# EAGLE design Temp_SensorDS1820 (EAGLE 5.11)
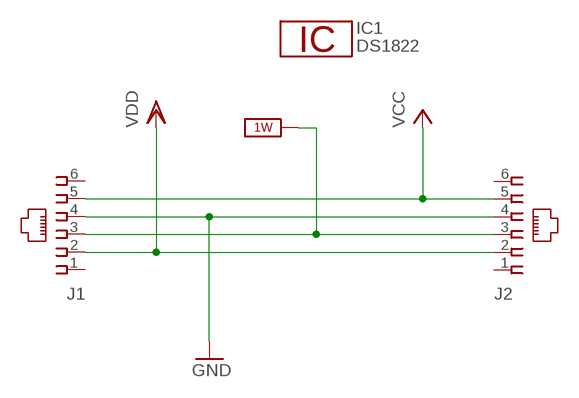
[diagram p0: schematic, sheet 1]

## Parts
IC1  DS1822  [TO92-]
J1  520243-3  [520243-3]
J2  520243-3  [520243-3]

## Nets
1W: J1.3 J2.3 ; supply symbol labelled 1W_SUP
GND: J1.4 J2.4
VCC [12V]: J1.5 J2.5
VDD: J1.2 J2.2
Unconnected: J1.1 J1.6 J2.1 J2.6

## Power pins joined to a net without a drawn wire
1W: IC1.2
GND: IC1.1
VDD: IC1.3

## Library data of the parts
IC1 = 1wire:DS1822: Econo Digital Thermometer This chip provides a onewire thermosensor with approx. 2°C accuracy. A programmable over/undertemperure alarm is available. Notes: Vdd must be applied for accurate measurements at low temperatures, as the parasite power circuit otherwise heats the sensor. If parasite power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
J1 J2 = con-amp:520243-3: AMP connector; OC_FARNELL: unknown; OC_NEWARK: unknown

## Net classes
0 default: width 0.381 mm, drill 0.762 mm
1 12V: width 0.381 mm, drill 0.762 mm

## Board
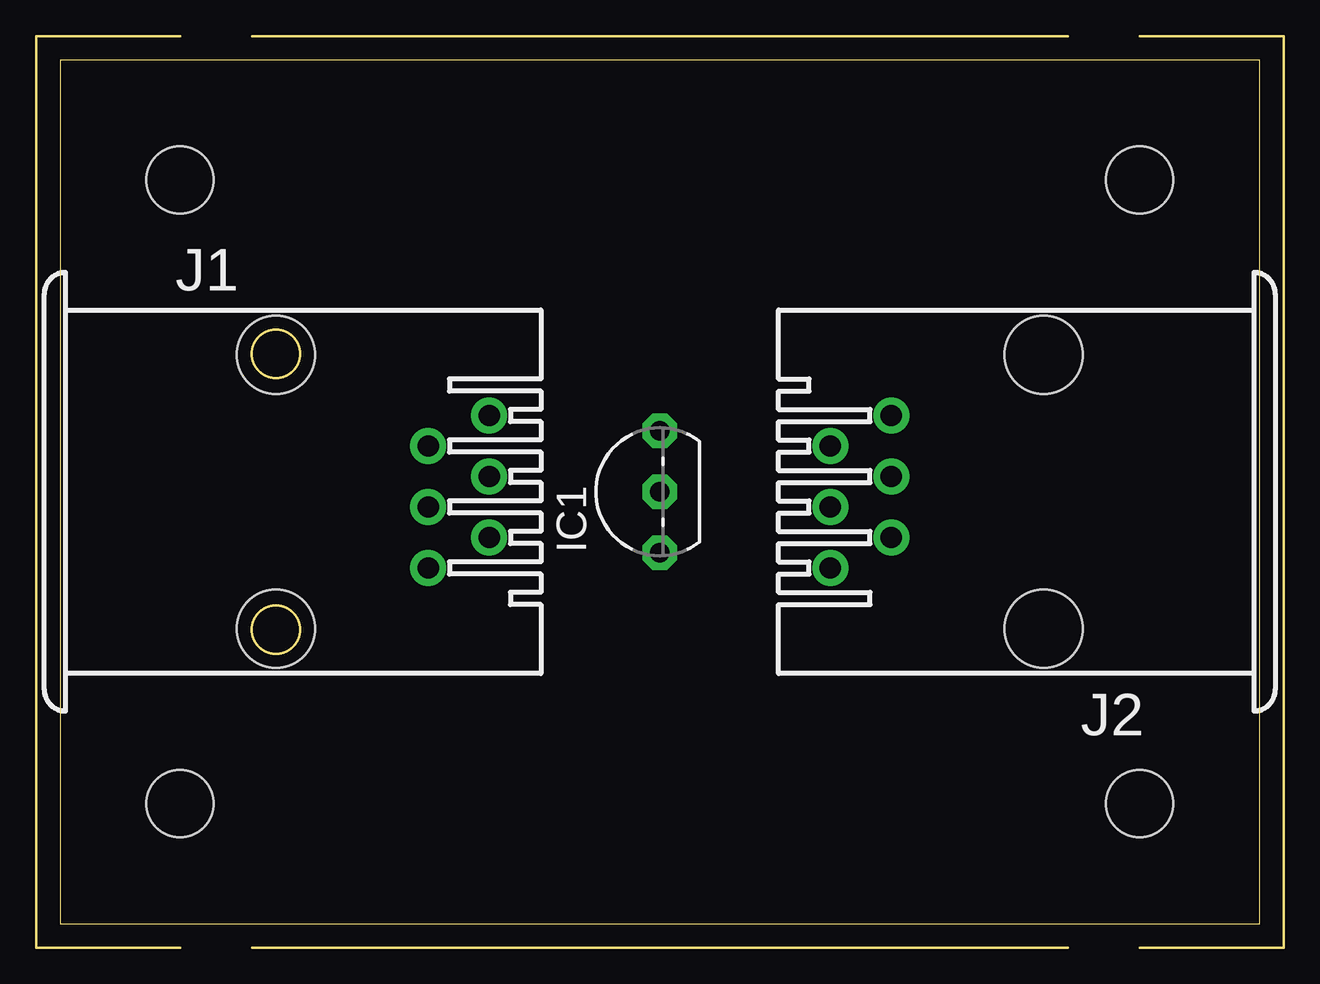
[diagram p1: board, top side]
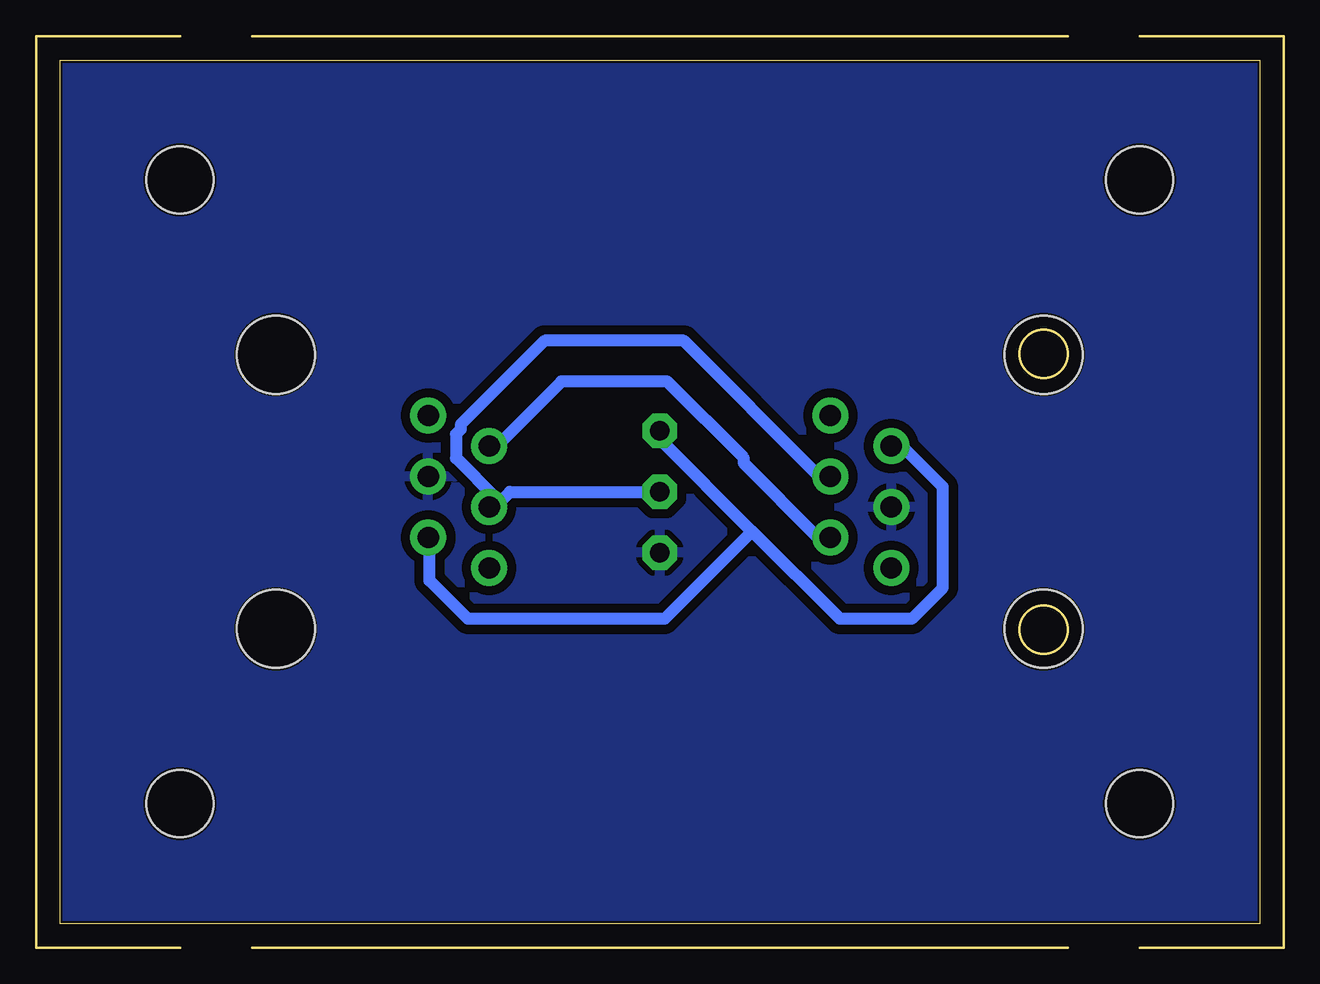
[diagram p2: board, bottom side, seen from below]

Size 50 x 36 mm. Coordinates in mm from the lower left corner, seen from the top.
Outline: 0,0 50,0 50,36 0,36 0,0
Copper layers (1*16): Top 0.035mm / dielectric 1.5mm / Bottom 0.035mm
Design rules "cnc_20mil_Tool0.15mm *": minimum track width 20mil, minimum drill 32mil, track to track 15mil, track to pad 12mil, pad to pad 15mil, via to via 15mil, smd to smd 10mil, copper to edge 4mil, drill to drill 16mil, minimum pad ring 12mil, minimum via ring 8mil, stop-mask expansion 8mil, vias tented up to drill 0mil, thermal gap 10mil
Holes 2.8 mm at 45,31 5,31 5,5 45,5
Milling: area 8,22.8 to 10,24.8; area 8,11.2 to 10,13.2; 8 lines

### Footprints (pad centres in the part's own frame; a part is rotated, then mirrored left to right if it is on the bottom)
TO92- = drill 0.813 octagon: 1 -2.54,0; 2 0,0; 3 2.54,0
520243-3 = drill 0.889 round: 1 -3.175,8.89; 2 -1.905,6.35; 3 -0.635,8.89; 4 0.635,6.35; 5 1.905,8.89; 6 3.175,6.35 | hole 3.251: -5.715,0; 5.715,0

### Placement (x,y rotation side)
IC1  25,18 90 top
J1  9,18 270 top
J2  41,18 90 top

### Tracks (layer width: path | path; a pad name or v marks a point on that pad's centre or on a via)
1W
  Bottom 0.508: IC1.2 31.25,18 32,17.25 J2.3 31.8,17.7 33.5,19.4 33.5,20.4 33.3,20.6 33.3,20.8 29.8,24.3 24,24.3 18.4,18.7 17.9,18.7 J1.3
GND
  pour Bottom: -0.5,36.5 50.5,36.5 50.38,-0.5 -0.5,-0.5
VCC
  Bottom 0.508: J1.5 18.4,16.1 21.5,19.2 21.5,19.4 24.7,22.6 29.1,22.6 31.7,20 32.1,20 J2.5
VDD
  Bottom 0.508: 21.15,16.35 17.5,12.7 14.5,12.7 13.2,14 13.2,18.2 14.9,19.9 15.3,19.9 J1.2 | 21.15,16.35 25,20.2 IC1.3 | J2.2 34.6,16 34.6,14.3 33,12.7 24.8,12.7 21.15,16.35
